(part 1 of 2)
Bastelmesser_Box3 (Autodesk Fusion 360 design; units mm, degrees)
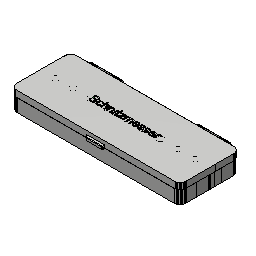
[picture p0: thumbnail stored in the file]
part number: 2025-11-06-15-49-21-213
part number: 2025-11-06-23-53-22-659
part number: 2025-11-06-23-55-04-899
base_feature "Basiselement1" bodies "lid_W150xD95xH20"
move "Verschieben1"
move "Verschieben2"
base_feature "Basiselement1" bodies "box_W150xD95xH20"
delete_face "Fläche löschen1"
delete_face "Fläche löschen2"
delete_face "Fläche löschen3"
delete_face "Fläche löschen4"
delete_face "Fläche löschen1"
delete_face "Fläche löschen2"
move "Verschieben3"
delete_face "Fläche löschen5"
delete_face "Fläche löschen6"
delete_face "Fläche löschen7"
delete_face "Fläche löschen8"
delete_face "Fläche löschen9"
delete_face "Fläche löschen10"
delete_face "Fläche löschen11"
delete_face "Fläche löschen12"
delete_face "Fläche löschen13"
move "Verschieben4"
sketch "Skizze1" plane through (0, 0, 22) normal (0, 0, 1) x axis (-1, 0, 0)
  line L1 (72.9999, 48.1497) -> (-73.0392, 48.1482)
  line L2 (73, 48.1497) -> (72.9999, 48.1497)
  line L3 (73.3517, 48.1236) -> (73, 48.1497)
  line L4 (73.7347, 48.038) -> (73.3517, 48.1236)
  line L5 (74.0994, 47.8936) -> (73.7347, 48.038)
  line L6 (74.4369, 47.694) -> (74.0994, 47.8936)
  line L7 (74.7396, 47.4435) -> (74.4369, 47.694)
  line L8 (74.9982, 47.15) -> (74.7396, 47.4435)
  line L9 (75.2083, 46.8191) -> (74.9982, 47.15)
  line L10 (75.364, 46.4591) -> (75.2083, 46.8191)
  line L11 (75.4616, 46.0789) -> (75.364, 46.4591)
  line L12 (75.4985, 45.6889) -> (75.4616, 46.0789)
  line L13 (75.5, -45.3503) -> (75.4985, 45.6889)
  line L14 (75.4739, -45.702) -> (75.5, -45.3503)
  line L15 (75.3883, -46.085) -> (75.4739, -45.702)
  line L16 (75.2439, -46.4497) -> (75.3883, -46.085)
  line L17 (75.0443, -46.7872) -> (75.2439, -46.4497)
  line L18 (74.795, -47.0886) -> (75.0443, -46.7872)
  line L19 (74.5005, -47.3484) -> (74.795, -47.0886)
  line L20 (74.1693, -47.5585) -> (74.5005, -47.3484)
  line L21 (73.8094, -47.7143) -> (74.1693, -47.5585)
  line L22 (73.4292, -47.8119) -> (73.8094, -47.7143)
  line L23 (73.0392, -47.8487) -> (73.4292, -47.8119)
  line L24 (-73, -47.8503) -> (73.0392, -47.8487)
  line L25 (-73.3517, -47.8242) -> (-73, -47.8503)
  line L26 (-73.7347, -47.7386) -> (-73.3517, -47.8242)
  line L27 (-74.0994, -47.5942) -> (-73.7347, -47.7386)
  line L28 (-74.4369, -47.3945) -> (-74.0994, -47.5942)
  line L29 (-74.7396, -47.144) -> (-74.4369, -47.3945)
  line L30 (-74.9982, -46.8506) -> (-74.7396, -47.144)
  line L31 (-75.2083, -46.5196) -> (-74.9982, -46.8506)
  line L32 (-75.364, -46.1597) -> (-75.2083, -46.5196)
  line L33 (-75.4616, -45.7795) -> (-75.364, -46.1597)
  line L34 (-75.4985, -45.3894) -> (-75.4616, -45.7795)
  line L35 (-75.5, 45.6498) -> (-75.4985, -45.3894)
  line L36 (-75.4739, 46.0014) -> (-75.5, 45.6498)
  line L37 (-75.3883, 46.3845) -> (-75.4739, 46.0014)
  line L38 (-75.2439, 46.7491) -> (-75.3883, 46.3845)
  line L39 (-75.0443, 47.0867) -> (-75.2439, 46.7491)
  line L40 (-74.795, 47.388) -> (-75.0443, 47.0867)
  line L41 (-74.5005, 47.6478) -> (-74.795, 47.388)
  line L42 (-74.1693, 47.858) -> (-74.5005, 47.6478)
  line L43 (-73.8094, 48.0138) -> (-74.1693, 47.858)
  line L44 (-73.4292, 48.1114) -> (-73.8094, 48.0138)
  line L45 (-73.0392, 48.1482) -> (-73.4292, 48.1114)
  line L46 (-78.4013, 47.5848) -> (-77.6325, 48.574)
  line L47 (-78.6417, 46.3723) -> (-78.4013, 47.5848)
  line L48 (-78.3254, 45.1517) -> (-78.6417, 46.3723)
  line L49 (-78.0289, 43.8727) -> (-78.3254, 45.1517)
  line L50 (-77.8472, 42.5936) -> (-78.0289, 43.8727)
  line L51 (-77.8018, 41.3145) -> (-77.8472, 42.5936)
  line L52 (-77.8979, 40.0354) -> (-77.8018, 41.3145)
  line L53 (-78.1243, 38.7563) -> (-77.8979, 40.0354)
  line L54 (-78.4541, 37.4772) -> (-78.1243, 38.7563)
  line L55 (-78.7587, 36.1981) -> (-78.4541, 37.4772)
  line L56 (-78.7368, 34.919) -> (-78.7587, 36.1981)
  line L57 (-78.3554, 33.64) -> (-78.7368, 34.919)
  line L58 (-78.05, 32.361) -> (-78.3554, 33.64)
  line L59 (-77.8568, 31.0819) -> (-78.05, 32.361)
  line L60 (-77.7985, 29.8028) -> (-77.8568, 31.0819)
  line L61 (-77.882, 28.5237) -> (-77.7985, 29.8028)
  line L62 (-78.0974, 27.2446) -> (-77.882, 28.5237)
  line L63 (-78.4192, 25.9655) -> (-78.0974, 27.2446)
  line L64 (-78.7572, 24.6864) -> (-78.4192, 25.9655)
  line L65 (-78.757, 23.4073) -> (-78.7572, 24.6864)
  line L66 (-78.386, 22.1283) -> (-78.757, 23.4073)
  line L67 (-78.072, 20.8492) -> (-78.386, 22.1283)
  line L68 (-77.8674, 19.5702) -> (-78.072, 20.8492)
  line L69 (-77.7963, 18.2911) -> (-77.8674, 19.5702)
  line L70 (-77.8671, 17.012) -> (-77.7963, 18.2911)
  line L71 (-78.0714, 15.7329) -> (-77.8671, 17.012)
  line L72 (-78.3849, 14.4538) -> (-78.0714, 15.7329)
  line L73 (-78.7556, 13.1747) -> (-78.3849, 14.4538)
  line L74 (-78.7555, 11.8956) -> (-78.7556, 13.1747)
  line L75 (-78.4172, 10.6165) -> (-78.7555, 11.8956)
  line L76 (-78.095, 9.3375) -> (-78.4172, 10.6165)
  line L77 (-77.8792, 8.0585) -> (-78.095, 9.3375)
  line L78 (-77.7954, 6.7794) -> (-77.8792, 8.0585)
  line L79 (-77.8533, 5.5003) -> (-77.7954, 6.7794)
  line L80 (-78.0462, 4.2212) -> (-77.8533, 5.5003)
  line L81 (-78.3513, 2.9421) -> (-78.0462, 4.2212)
  line L82 (-78.7323, 1.6629) -> (-78.3513, 2.9421)
  line L83 (-78.7539, 0.3839) -> (-78.7323, 1.6629)
  line L84 (-78.4489, -0.8952) -> (-78.7539, 0.3839)
  line L85 (-78.1188, -2.1742) -> (-78.4489, -0.8952)
  line L86 (-77.8921, -3.4533) -> (-78.1188, -2.1742)
  line L87 (-77.7956, -4.7323) -> (-77.8921, -3.4533)
  line L88 (-77.8407, -6.0114) -> (-77.7956, -4.7323)
  line L89 (-78.0221, -7.2905) -> (-77.8407, -6.0114)
  line L90 (-78.3182, -8.5696) -> (-78.0221, -7.2905)
  line L91 (-78.6941, -9.8488) -> (-78.3182, -8.5696)
  line L92 (-78.7524, -11.1279) -> (-78.6941, -9.8488)
  line L93 (-78.4812, -12.4069) -> (-78.7524, -11.1279)
  line L94 (-78.1435, -13.6859) -> (-78.4812, -12.4069)
  line L95 (-77.906, -14.965) -> (-78.1435, -13.6859)
  line L96 (-77.797, -16.244) -> (-77.906, -14.965)
  line L97 (-77.8292, -17.5231) -> (-77.797, -16.244)
  line L98 (-77.9988, -18.8022) -> (-77.8292, -17.5231)
  line L99 (-78.2858, -20.0814) -> (-77.9988, -18.8022)
  line L100 (-78.6562, -21.3605) -> (-78.2858, -20.0814)
  line L101 (-78.7508, -22.6396) -> (-78.6562, -21.3605)
  line L102 (-78.5141, -23.9186) -> (-78.7508, -22.6396)
  line L103 (-78.169, -25.1977) -> (-78.5141, -23.9186)
  line L104 (-77.9211, -26.4767) -> (-78.169, -25.1977)
  line L105 (-77.7996, -27.7558) -> (-77.9211, -26.4767)
  line L106 (-77.8188, -29.0348) -> (-77.7996, -27.7558)
  line L107 (-77.9766, -30.3139) -> (-77.8188, -29.0348)
  line L108 (-78.2541, -31.5931) -> (-77.9766, -30.3139)
  line L109 (-78.6186, -32.8722) -> (-78.2541, -31.5931)
  line L110 (-78.7493, -34.1513) -> (-78.6186, -32.8722)
  line L111 (-78.5473, -35.4303) -> (-78.7493, -34.1513)
  line L112 (-78.1953, -36.7094) -> (-78.5473, -35.4303)
  line L113 (-77.9372, -37.9884) -> (-78.1953, -36.7094)
  line L114 (-77.8033, -39.2675) -> (-77.9372, -37.9884)
  line L115 (-77.8096, -40.5466) -> (-77.8033, -39.2675)
  line L116 (-77.9553, -41.8257) -> (-77.8096, -40.5466)
  line L117 (-78.2231, -43.1048) -> (-77.9553, -41.8257)
  line L118 (-78.5814, -44.3839) -> (-78.2231, -43.1048)
  line L119 (-78.7497, -45.6324) -> (-78.5814, -44.3839)
  line L120 (-78.3789, -46.8062) -> (-78.7497, -45.6324)
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  dimension "d1" = -3.25
extrude "Extrusion1" new body sketch "Skizze1" against normal blind 22
combine "Kombinieren1"
work_plane "Arbeitsebene1" AlongDistance 0
extrude "Extrusion1" add of existing geometry blind 5.536
work_plane "Arbeitsebene1" AlongDistance -18.9338
split "Teilen1" bodies "lid_W150xD95xH20 (1)"
work_plane "Arbeitsebene2" AlongDistance 47
split "Teilen2" bodies "lid_W150xD95xH20 (1) (1)"
move "Verschieben1"
combine "Kombinieren2" bodies "box_W150xD95xH20 (2) (1)"
move "Verschieben5"
combine "Kombinieren1" bodies "lid_W150xD95xH20 (1) (1)"
delete_face "Fläche löschen14"
work_plane "Arbeitsebene2" AlongDistance 0
split "Teilen4" bodies "box_W150xD95xH20 (1)", "box_W150xD95xH20 (3)", "box_W150xD95xH20 (4)", "box_W150xD95xH20 (5)", "box_W150xD95xH20 (6)", "box_W150xD95xH20 (7)", "box_W150xD95xH20 (8)", "box_W150xD95xH20 (9)"
remove_body "Körper entfernen3"
remove_body "Körper entfernen4"
offset_faces "Flächen versetzen1" distance 10
offset_faces "Flächen versetzen2" distance -10
remove_body "Körper entfernen5"
remove_body "Körper entfernen6"
remove_body "Körper entfernen7"
remove_body "Körper entfernen8"
remove_body "Körper entfernen9"
remove_body "Körper entfernen10"
remove_body "Körper entfernen11"
remove_body "Körper entfernen12"
remove_body "Körper entfernen13"
remove_body "Körper entfernen14"
remove_body "Körper entfernen15"
remove_body "Körper entfernen16"
work_plane "Arbeitsebene3" AlongDistance 0
split "Teilen5" bodies "box_W150xD95xH20 (1)", "box_W150xD95xH20 (2)", "box_W150xD95xH20 (3)"
remove_body "Körper entfernen17"
remove_body "Körper entfernen18"
remove_body "Körper entfernen19"
sketch "Skizze2" plane through (0, 0, 22) normal (0, 0, 1) x axis (-1, 0, 0)
  line L1 (75.5, -45.3503) -> (75.4997, -28.0662)
  line L2 (75.4739, -45.702) -> (75.5, -45.3503)
  line L3 (75.3883, -46.085) -> (75.4739, -45.702)
  line L4 (75.2439, -46.4497) -> (75.3883, -46.085)
  line L5 (75.0443, -46.7872) -> (75.2439, -46.4497)
  line L6 (74.795, -47.0886) -> (75.0443, -46.7872)
  line L7 (74.5005, -47.3484) -> (74.795, -47.0886)
  line L8 (74.1693, -47.5585) -> (74.5005, -47.3484)
  line L9 (73.8094, -47.7143) -> (74.1693, -47.5585)
  line L10 (73.4292, -47.8119) -> (73.8094, -47.7143)
  line L11 (73.0392, -47.8487) -> (73.4292, -47.8119)
  line L12 (-73, -47.8503) -> (73.0392, -47.8487)
  line L13 (-73.3517, -47.8242) -> (-73, -47.8503)
  line L14 (-73.7347, -47.7386) -> (-73.3517, -47.8242)
  line L15 (-74.0994, -47.5942) -> (-73.7347, -47.7386)
  line L16 (-74.4369, -47.3945) -> (-74.0994, -47.5942)
  line L17 (-74.7396, -47.144) -> (-74.4369, -47.3945)
  line L18 (-74.9982, -46.8506) -> (-74.7396, -47.144)
  line L19 (-75.2083, -46.5196) -> (-74.9982, -46.8506)
  line L20 (-75.364, -46.1597) -> (-75.2083, -46.5196)
  line L21 (-75.4616, -45.7795) -> (-75.364, -46.1597)
  line L22 (-75.4985, -45.3894) -> (-75.4616, -45.7795)
  line L23 (-75.4988, -28.0662) -> (-75.4985, -45.3894)
  line L24 (-75.4995, -28.0662) -> (-75.4988, -28.0662)
  line L25 (-75.5, -1.3502) -> (-75.4995, -28.0662)
  line L26 (-75.4739, -0.9986) -> (-75.5, -1.3502)
  line L27 (-75.3883, -0.6155) -> (-75.4739, -0.9986)
  line L28 (-75.2439, -0.2509) -> (-75.3883, -0.6155)
  line L29 (-75.0443, 0.0867) -> (-75.2439, -0.2509)
  line L30 (-74.795, 0.388) -> (-75.0443, 0.0867)
  line L31 (-74.5005, 0.6478) -> (-74.795, 0.388)
  line L32 (-74.1693, 0.858) -> (-74.5005, 0.6478)
  line L33 (-73.8094, 1.0138) -> (-74.1693, 0.858)
  line L34 (-73.4292, 1.1114) -> (-73.8094, 1.0138)
  line L35 (-73.0392, 1.1482) -> (-73.4292, 1.1114)
  line L36 (72.9999, 1.1497) -> (-73.0392, 1.1482)
  line L37 (73, 1.1497) -> (72.9999, 1.1497)
  line L38 (73.3517, 1.1236) -> (73, 1.1497)
  line L39 (73.7347, 1.038) -> (73.3517, 1.1236)
  line L40 (74.0994, 0.8936) -> (73.7347, 1.038)
  line L41 (74.4369, 0.694) -> (74.0994, 0.8936)
  line L42 (74.7396, 0.4435) -> (74.4369, 0.694)
  line L43 (74.9982, 0.15) -> (74.7396, 0.4435)
  line L44 (75.2083, -0.1809) -> (74.9982, 0.15)
  line L45 (75.364, -0.5409) -> (75.2083, -0.1809)
  line L46 (75.4616, -0.9211) -> (75.364, -0.5409)
  line L47 (75.4985, -1.3111) -> (75.4616, -0.9211)
  line L48 (75.4989, -28.0662) -> (75.4985, -1.3111)
  line L49 (75.4997, -28.0662) -> (75.4989, -28.0662)
  line L50 (-73.1923, 4.3982) -> (73.1205, 4.3997)
  line L51 (-73.9894, 4.3229) -> (-73.1923, 4.3982)
  line L52 (-74.8653, 4.0981) -> (-73.9894, 4.3229)
  line L53 (-75.6949, 3.7391) -> (-74.8653, 4.0981)
  line L54 (-76.4582, 3.2546) -> (-75.6949, 3.7391)
  line L55 (-77.1366, 2.6563) -> (-76.4582, 3.2546)
  line L56 (-77.7116, 1.961) -> (-77.1366, 2.6563)
  line L57 (-78.1715, 1.1835) -> (-77.7116, 1.961)
  line L58 (-78.5043, 0.343) -> (-78.1715, 1.1835)
  line L59 (-78.6974, -0.5214) -> (-78.5043, 0.343)
  line L60 (-78.75, -1.2298) -> (-78.6974, -0.5214)
  line L61 (-78.7498, -10.7646) -> (-78.75, -1.2298)
  line L62 (-78.7587, -10.8019) -> (-78.7498, -10.7646)
  line L63 (-78.7498, -11.3207) -> (-78.7587, -10.8019)
  line L64 (-78.7496, -22.2851) -> (-78.7498, -11.3207)
  line L65 (-78.7572, -22.3136) -> (-78.7496, -22.2851)
  line L66 (-78.757, -23.5927) -> (-78.7572, -22.3136)
  line L67 (-78.7496, -23.6181) -> (-78.757, -23.5927)
  line L68 (-78.7495, -28.0662) -> (-78.7496, -23.6181)
  line L69 (-78.7488, -28.0662) -> (-78.7495, -28.0662)
  line L70 (-78.7487, -34.1454) -> (-78.7488, -28.0662)
  line L71 (-78.7493, -34.1513) -> (-78.7487, -34.1454)
  line L72 (-78.7487, -34.1551) -> (-78.7493, -34.1513)
  line L73 (-78.7485, -45.5426) -> (-78.7487, -34.1551)
  line L74 (-78.744, -45.5898) -> (-78.7485, -45.5426)
  line L75 (-78.7497, -45.6324) -> (-78.744, -45.5898)
  line L76 (-78.7358, -45.6765) -> (-78.7497, -45.6324)
  line L77 (-78.6732, -46.3397) -> (-78.7358, -45.6765)
  line L78 (-78.4484, -47.2156) -> (-78.6732, -46.3397)
  line L79 (-78.0894, -48.0451) -> (-78.4484, -47.2156)
  line L80 (-77.6054, -48.8077) -> (-78.0894, -48.0451)
  line L81 (-77.0087, -49.4847) -> (-77.6054, -48.8077)
  line L82 (-76.3119, -50.0615) -> (-77.0087, -49.4847)
  line L83 (-75.5337, -50.5217) -> (-76.3119, -50.0615)
  line L84 (-74.6932, -50.8545) -> (-75.5337, -50.5217)
  line L85 (-73.8289, -51.0477) -> (-74.6932, -50.8545)
  line L86 (-73.1205, -51.1003) -> (-73.8289, -51.0477)
  line L87 (-70.6456, -51.1002) -> (-73.1205, -51.1003)
  line L88 (-70.5833, -51.1101) -> (-70.6456, -51.1002)
  line L89 (-70.4873, -51.1002) -> (-70.5833, -51.1101)
  line L90 (-64.3433, -51.1002) -> (-70.4873, -51.1002)
  line L91 (-64.3433, -51.8441) -> (-64.3433, -51.1002)
  line L92 (-58.3433, -51.8441) -> (-64.3433, -51.8441)
  line L93 (-58.3433, -51.1001) -> (-58.3433, -51.8441)
  line L94 (-47.5994, -51.1) -> (-58.3433, -51.1001)
  line L95 (-47.561, -51.1081) -> (-47.5994, -51.1)
  line L96 (-47.3834, -51.1) -> (-47.561, -51.1081)
  line L97 (-41.3433, -51.0999) -> (-47.3834, -51.1)
  line L98 (-41.3433, -51.8441) -> (-41.3433, -51.0999)
  line L99 (-35.3433, -51.8441) -> (-41.3433, -51.8441)
  line L100 (-35.3433, -51.0999) -> (-35.3433, -51.8441)
  line L101 (-24.5609, -51.0998) -> (-35.3433, -51.0999)
  line L102 (-24.5366, -51.1062) -> (-24.5609, -51.0998)
  line L103 (-23.2573, -51.1061) -> (-24.5366, -51.1062)
  line L104 (-23.2355, -51.0997) -> (-23.2573, -51.1061)
  line L105 (-13.0448, -51.0996) -> (-23.2355, -51.0997)
  line L106 (-13.0255, -51.1052) -> (-13.0448, -51.0996)
  line L107 (-11.7462, -51.1051) -> (-13.0255, -51.1052)
  line L108 (-11.7254, -51.0996) -> (-11.7462, -51.1051)
  line L109 (-0.5072, -51.0995) -> (-11.7254, -51.0996)
  line L110 (-0.2329, -51.1041) -> (-0.5072, -51.0995)
  line L111 (-0.2134, -51.0995) -> (-0.2329, -51.1041)
  line L112 (11.1949, -51.0994) -> (-0.2134, -51.0995)
  line L113 (11.2782, -51.1032) -> (11.1949, -51.0994)
  line L114 (11.2962, -51.0994) -> (11.2782, -51.1032)
  line L115 (22.7494, -51.0993) -> (11.2962, -51.0994)
  line L116 (22.7894, -51.1022) -> (22.7494, -51.0993)
  line L117 (22.8053, -51.0993) -> (22.7894, -51.1022)
  line L118 (34.2821, -51.0991) -> (22.8053, -51.0993)
  line L119 (34.3027, -51.1012) -> (34.2821, -51.0991)
  line L120 (34.316, -51.0991) -> (34.3027, -51.1012)
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  dimension "d14" = -1.25
extrude "Extrusion2" cut sketch "Skizze2" against normal blind 10
sketch "Skizze3" plane through (0, 0, 10) normal (0, 0, -1) x axis (1, 0, 0)
  line L1 (-73.1205, 4.3997) -> (73.1923, 4.3982)
  line L2 (-73.8289, 4.3472) -> (-73.1205, 4.3997)
  line L3 (-74.6933, 4.154) -> (-73.8289, 4.3472)
  line L4 (-75.5337, 3.8212) -> (-74.6933, 4.154)
  line L5 (-76.3118, 3.361) -> (-75.5337, 3.8212)
  line L6 (-77.0087, 2.7842) -> (-76.3118, 3.361)
  line L7 (-77.6054, 2.1072) -> (-77.0087, 2.7842)
  line L8 (-78.0894, 1.3445) -> (-77.6054, 2.1072)
  line L9 (-78.4484, 0.515) -> (-78.0894, 1.3445)
  line L10 (-78.6732, -0.3609) -> (-78.4484, 0.515)
  line L11 (-78.7358, -1.024) -> (-78.6732, -0.3609)
  line L12 (-78.7497, -1.0681) -> (-78.7358, -1.024)
  line L13 (-78.744, -1.1107) -> (-78.7497, -1.0681)
  line L14 (-78.7485, -1.1579) -> (-78.744, -1.1107)
  line L15 (-78.7487, -12.5454) -> (-78.7485, -1.1579)
  line L16 (-78.7493, -12.5492) -> (-78.7487, -12.5454)
  line L17 (-78.7487, -12.5551) -> (-78.7493, -12.5492)
  line L18 (-78.7488, -24.0504) -> (-78.7487, -12.5551)
  line L19 (-78.7508, -24.0609) -> (-78.7488, -24.0504)
  line L20 (-78.7488, -24.0874) -> (-78.7508, -24.0609)
  line L21 (-78.7489, -28.0662) -> (-78.7488, -24.0874)
  line L22 (-78.7497, -28.0662) -> (-78.7489, -28.0662)
  line L23 (-78.7498, -35.3798) -> (-78.7497, -28.0662)
  line L24 (-78.7587, -35.8986) -> (-78.7498, -35.3798)
  line L25 (-78.7498, -35.936) -> (-78.7587, -35.8986)
  line L26 (-78.75, -45.4708) -> (-78.7498, -35.936)
  line L27 (-78.6974, -46.1792) -> (-78.75, -45.4708)
  line L28 (-78.5043, -47.0435) -> (-78.6974, -46.1792)
  line L29 (-78.1715, -47.884) -> (-78.5043, -47.0435)
  line L30 (-77.7116, -48.6616) -> (-78.1715, -47.884)
  line L31 (-77.1366, -49.3569) -> (-77.7116, -48.6616)
  line L32 (-76.4582, -49.9551) -> (-77.1366, -49.3569)
  line L33 (-75.6949, -50.4396) -> (-76.4582, -49.9551)
  line L34 (-74.8653, -50.7986) -> (-75.6949, -50.4396)
  line L35 (-73.9894, -51.0234) -> (-74.8653, -50.7986)
  line L36 (-73.1923, -51.0987) -> (-73.9894, -51.0234)
  line L37 (-64.6567, -51.0988) -> (-73.1923, -51.0987)
  line L38 (-64.6567, -50.2369) -> (-64.6567, -51.0988)
  line L39 (-64.4198, -50.2144) -> (-64.6567, -50.2369)
  line L40 (-63.7212, -50.1482) -> (-64.4198, -50.2144)
  line L41 (-62.4419, -50.1678) -> (-63.7212, -50.1482)
  line L42 (-61.1626, -50.3258) -> (-62.4419, -50.1678)
  line L43 (-59.8834, -50.6036) -> (-61.1626, -50.3258)
  line L44 (-59.534, -50.7032) -> (-59.8834, -50.6036)
  line L45 (-58.6567, -50.9534) -> (-59.534, -50.7032)
  line L46 (-58.6567, -51.0989) -> (-58.6567, -50.9534)
  line L47 (-57.329, -51.0989) -> (-58.6567, -51.0989)
  line L48 (-57.3249, -51.0993) -> (-57.329, -51.0989)
  line L49 (-57.3223, -51.0989) -> (-57.3249, -51.0993)
  line L50 (-45.8235, -51.099) -> (-57.3223, -51.0989)
  line L51 (-45.8138, -51.1003) -> (-45.8235, -51.099)
  line L52 (-45.8041, -51.099) -> (-45.8138, -51.1003)
  line L53 (-41.6567, -51.0991) -> (-45.8041, -51.099)
  line L54 (-41.6567, -50.2713) -> (-41.6567, -51.0991)
  line L55 (-41.4118, -50.2434) -> (-41.6567, -50.2713)
  line L56 (-40.6967, -50.162) -> (-41.4118, -50.2434)
  line L57 (-39.4174, -50.1556) -> (-40.6967, -50.162)
  line L58 (-38.1382, -50.2893) -> (-39.4174, -50.1556)
  line L59 (-36.8589, -50.5474) -> (-38.1382, -50.2893)
  line L60 (-36.5133, -50.6425) -> (-36.8589, -50.5474)
  line L61 (-35.6567, -50.8782) -> (-36.5133, -50.6425)
  line L62 (-35.6567, -51.0991) -> (-35.6567, -50.8782)
  line L63 (-34.316, -51.0991) -> (-35.6567, -51.0991)
  line L64 (-34.3027, -51.1012) -> (-34.316, -51.0991)
  line L65 (-34.2821, -51.0991) -> (-34.3027, -51.1012)
  line L66 (-22.8053, -51.0993) -> (-34.2821, -51.0991)
  line L67 (-22.7894, -51.1022) -> (-22.8053, -51.0993)
  line L68 (-22.7494, -51.0993) -> (-22.7894, -51.1022)
  line L69 (-11.2962, -51.0994) -> (-22.7494, -51.0993)
  line L70 (-11.2782, -51.1032) -> (-11.2962, -51.0994)
  line L71 (-11.1949, -51.0994) -> (-11.2782, -51.1032)
  line L72 (0.2134, -51.0995) -> (-11.1949, -51.0994)
  line L73 (0.2329, -51.1041) -> (0.2134, -51.0995)
  line L74 (0.5072, -51.0995) -> (0.2329, -51.1041)
  line L75 (11.7254, -51.0996) -> (0.5072, -51.0995)
  line L76 (11.7462, -51.1051) -> (11.7254, -51.0996)
  line L77 (13.0255, -51.1052) -> (11.7462, -51.1051)
  line L78 (13.0448, -51.0996) -> (13.0255, -51.1052)
  line L79 (23.2355, -51.0997) -> (13.0448, -51.0996)
  line L80 (23.2573, -51.1061) -> (23.2355, -51.0997)
  line L81 (24.5366, -51.1062) -> (23.2573, -51.1061)
  line L82 (24.5609, -51.0998) -> (24.5366, -51.1062)
  line L83 (35.3433, -51.0999) -> (24.5609, -51.0998)
  line L84 (35.3433, -51.0951) -> (35.3433, -51.0999)
  line L85 (35.4662, -51.0972) -> (35.3433, -51.0951)
  line L86 (35.5533, -51.0987) -> (35.4662, -51.0972)
  line L87 (36.0477, -51.1072) -> (35.5533, -51.0987)
  line L88 (37.327, -50.8025) -> (36.0477, -51.1072)
  line L89 (38.6063, -50.4726) -> (37.327, -50.8025)
  line L90 (39.8856, -50.2462) -> (38.6063, -50.4726)
  line L91 (41.1648, -50.15) -> (39.8856, -50.2462)
  line L92 (41.3433, -50.1563) -> (41.1648, -50.15)
  line L93 (41.3433, -51.0999) -> (41.3433, -50.1563)
  line L94 (47.3834, -51.1) -> (41.3433, -51.0999)
  line L95 (47.561, -51.1081) -> (47.3834, -51.1)
  line L96 (47.5994, -51.1) -> (47.561, -51.1081)
  line L97 (58.3433, -51.1001) -> (47.5994, -51.1)
  line L98 (58.3433, -51.055) -> (58.3433, -51.1001)
  line L99 (58.4907, -51.066) -> (58.3433, -51.055)
  line L100 (58.5592, -51.071) -> (58.4907, -51.066)
  line L101 (59.0722, -51.1091) -> (58.5592, -51.071)
  line L102 (60.3514, -50.8726) -> (59.0722, -51.1091)
  line L103 (61.6307, -50.5278) -> (60.3514, -50.8726)
  line L104 (62.91, -50.2802) -> (61.6307, -50.5278)
  line L105 (64.1893, -50.159) -> (62.91, -50.2802)
  line L106 (64.3433, -50.1613) -> (64.1893, -50.159)
  line L107 (64.3433, -51.1002) -> (64.3433, -50.1613)
  line L108 (70.4873, -51.1002) -> (64.3433, -51.1002)
  line L109 (70.5833, -51.1101) -> (70.4873, -51.1002)
  line L110 (70.6456, -51.1002) -> (70.5833, -51.1101)
  line L111 (73.1205, -51.1003) -> (70.6456, -51.1002)
  line L112 (73.8289, -51.0477) -> (73.1205, -51.1003)
  line L113 (74.6932, -50.8545) -> (73.8289, -51.0477)
  line L114 (75.5337, -50.5217) -> (74.6932, -50.8545)
  line L115 (76.3119, -50.0615) -> (75.5337, -50.5217)
  line L116 (77.0087, -49.4847) -> (76.3119, -50.0615)
  line L117 (77.6054, -48.8077) -> (77.0087, -49.4847)
  line L118 (78.0894, -48.0451) -> (77.6054, -48.8077)
  line L119 (78.4484, -47.2156) -> (78.0894, -48.0451)
  line L120 (78.6732, -46.3397) -> (78.4484, -47.2156)
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  point P48 (-58.6567, -51.0989)
  point P149 (-58.6567, -51.0989)
  point P64 (-35.6567, -51.0991)
  point P153 (-35.6567, -51.0991)
  point P95 (41.3433, -51.0999)
  point P157 (41.3433, -51.0999)
  point P109 (64.3433, -51.1002)
  point P161 (64.3433, -51.1002)
  coincident P48 P149
  coincident P64 P153
  coincident P95 P157
  coincident P109 P161
extrude "Extrusion3" add sketch "Skizze3" against normal blind 5.717
extrude "Extrusion4" add sketch "Skizze3" against normal blind 4.878
extrude "Extrusion5" add sketch "Skizze3" against normal blind 5.291
extrude "Extrusion6" add sketch "Skizze3" against normal blind 5.325
sketch "Skizze4" plane through (0, 0, 22) normal (0, 0, 1) x axis (-1, 0, 0)
work_plane "Arbeitsebene4" AlongDistance 0
sketch "Skizze5" plane through (0, 0, 22) normal (0, 0, 1) x axis (1, 0, 0)
  line L1 (73.0981, -2.3982) -> (-73.0463, -2.3997)
  line L2 (73.6447, -2.3466) -> (73.0981, -2.3982)
  line L3 (74.2155, -2.2001) -> (73.6447, -2.3466)
  line L4 (74.7561, -1.9661) -> (74.2155, -2.2001)
  line L5 (75.2534, -1.6505) -> (74.7561, -1.9661)
  line L6 (75.6956, -1.2605) -> (75.2534, -1.6505)
  line L7 (76.0702, -0.8076) -> (75.6956, -1.2605)
  line L8 (76.3699, -0.3008) -> (76.0702, -0.8076)
  line L9 (76.5868, 0.2469) -> (76.3699, -0.3008)
  line L10 (76.7137, 0.815) -> (76.5868, 0.2469)
  line L11 (76.75, 1.3039) -> (76.7137, 0.815)
  line L12 (76.7495, 29.3162) -> (76.75, 1.3039)
  line L13 (76.7487, 29.3162) -> (76.7495, 29.3162)
  line L14 (76.7485, 45.4483) -> (76.7487, 29.3162)
  line L15 (76.6968, 45.9949) -> (76.7485, 45.4483)
  line L16 (76.5503, 46.5658) -> (76.6968, 45.9949)
  line L17 (76.3164, 47.1063) -> (76.5503, 46.5658)
  line L18 (76.001, 47.6033) -> (76.3164, 47.1063)
  line L19 (75.6123, 48.0443) -> (76.001, 47.6033)
  line L20 (75.1581, 48.4203) -> (75.6123, 48.0443)
  line L21 (74.6511, 48.7202) -> (75.1581, 48.4203)
  line L22 (74.1034, 48.937) -> (74.6511, 48.7202)
  line L23 (73.5352, 49.064) -> (74.1034, 48.937)
  line L24 (73.0463, 49.1003) -> (73.5352, 49.064)
  line L25 (-73.0981, 49.0987) -> (73.0463, 49.1003)
  line L26 (-73.6446, 49.0471) -> (-73.0981, 49.0987)
  line L27 (-74.2155, 48.9006) -> (-73.6446, 49.0471)
  line L28 (-74.7561, 48.6666) -> (-74.2155, 48.9006)
  line L29 (-75.2534, 48.351) -> (-74.7561, 48.6666)
  line L30 (-75.6956, 47.961) -> (-75.2534, 48.351)
  line L31 (-76.0702, 47.5081) -> (-75.6956, 47.961)
  line L32 (-76.3699, 47.0013) -> (-76.0702, 47.5081)
  line L33 (-76.5868, 46.4537) -> (-76.3699, 47.0013)
  line L34 (-76.7137, 45.8855) -> (-76.5868, 46.4537)
  line L35 (-76.75, 45.3967) -> (-76.7137, 45.8855)
  line L36 (-76.7497, 26.8162) -> (-76.75, 45.3967)
  line L37 (-76.7489, 26.8162) -> (-76.7497, 26.8162)
  line L38 (-76.7485, 1.2522) -> (-76.7489, 26.8162)
  line L39 (-76.6968, 0.7056) -> (-76.7485, 1.2522)
  line L40 (-76.5503, 0.1347) -> (-76.6968, 0.7056)
  line L41 (-76.3164, -0.4058) -> (-76.5503, 0.1347)
  line L42 (-76.001, -0.9028) -> (-76.3164, -0.4058)
  line L43 (-75.6123, -1.3438) -> (-76.001, -0.9028)
  line L44 (-75.158, -1.7198) -> (-75.6123, -1.3438)
  line L45 (-74.6511, -2.0196) -> (-75.158, -1.7198)
  line L46 (-74.1034, -2.2365) -> (-74.6511, -2.0196)
  line L47 (-73.5352, -2.3634) -> (-74.1034, -2.2365)
  line L48 (-73.0463, -2.3997) -> (-73.5352, -2.3634)
  line L49 (55.7492, 23.3754) -> (76.7492, 23.3761)
  line L50 (55.7492, 33.8244) -> (55.7492, 15.5898)
  line L51 (14.7491, 26.378) -> (76.7491, 26.378)
  line L52 (-42.2502, 19.6259) -> (76.7498, 19.63)
  line L53 (14.7491, 33.747) -> (14.7491, 19.6279)
  line L54 (-42.2507, 32.7176) -> (-42.2502, 19.6259)
  line L55 (0.0258, 9.2563) -> (0.0259, -3.399)
  line L56 (73.0981, -3.3982) -> (-73.0463, -3.3997)
  line L57 (-3.5241, -2.399) -> (-3.5241, -0.4365)
  line L58 (3.5759, -2.3989) -> (3.5759, -0.4365)
  line L59 (-76.7485, 3.79) -> (-74.2023, 3.7821)
  line L60 (-70.588, -2.3997) -> (-70.5868, 0.1537)
  line L61 (-76.7485, 3.79) -> (-76.7485, 4.3758)
  line L62 (70.7336, -2.3982) -> (70.7209, 0.195)
  line L63 (76.75, 3.7685) -> (74.2623, 3.7625)
  line L64 (72.6939, -2.3982) -> (70.7336, -2.3982)
  line L65 (-72.5481, -2.3997) -> (-70.588, -2.3997)
  line L66 (-76.7485, 1.8514) -> (-76.7485, 3.79)
  line L67 (-2.3089, -2.399) -> (-3.5241, -2.399)
  line L68 (2.3606, -2.3989) -> (3.5759, -2.3989)
  line L69 (76.75, 3.7685) -> (76.6222, 3.7681)
  line L70 (76.75, 3.7685) -> (76.75, 1.9891)
  circle C1 centre (0.0259, -0.4365) radius 3.05
  arc A1 centre (-73.6899, 0.5362) radius 3.4648 clockwise from (-73.6883, 4.0011) to (-73.654, 4.0009)
  arc A2 centre (0.0259, -0.4365) radius 3.55 clockwise from (-3.5241, -0.4365) to (3.5759, -0.4365)
  arc A3 centre (-73.0062, 1.3434) radius 4.7433 clockwise from (-73.057, -3.3997) to (-77.7482, 1.2278)
  circle C2 centre (-74.2135, 0.1554) radius 3.05
  arc A4 centre (-74.2135, 0.1554) radius 3.6267 clockwise from (-74.2023, 3.7821) to (-70.5868, 0.1537)
  arc A5 centre (73.0069, 1.344) radius 4.7433 clockwise from (77.7499, 1.2932) to (73.1224, -3.3979)
  circle C3 centre (74.2708, 0.2125) radius 3.05
  arc A6 centre (74.2708, 0.2125) radius 3.55 clockwise from (76.7499, 2.7535) to (76.75, 2.7534)
  arc A7 centre (74.2708, 0.2125) radius 3.55 clockwise from (70.7209, 0.195) to (74.2623, 3.7625)
  point P58 (14.7491, 19.6279)
  point P64 (0.0259, -3.399)
  point P63 (0.0259, -0.4365)
  point P74 (-3.5241, -2.399)
  point P76 (3.5759, -2.3989)
  point P84 (-70.5868, 0.1537)
  point P85 (-70.588, -2.3997)
  point P86 (-70.5868, 0.1537)
  point P92 (70.7209, 0.195)
  point P93 (70.7336, -2.3982)
  point P94 (74.2623, 3.7625)
  point P98 (72.6939, -2.3982)
  point P99 (-72.5481, -2.3997)
  point P100 (-76.7485, 1.8514)
  point P101 (-2.3089, -2.399)
  point P102 (2.3606, -2.3989)
  point P103 (76.6222, 3.7681)
  point P104 (76.75, 3.7685)
  point P105 (76.75, 1.9891)
  point P50 (76.7492, 23.3761)
  point P51 (55.7492, 23.3754)
  point P54 (76.7491, 26.378)
  point P55 (14.7491, 26.378)
  point P56 (76.7498, 19.63)
  point P57 (-42.2502, 19.6259)
  vertical L50
  perpendicular L50 L51
  coincident L52 P58
  perpendicular L52 L54
  midpoint P64 L56
  perpendicular L55 L56
  coincident P63 L55
  coincident L1 P74
  perpendicular L1 L57
  coincident L1 P76
  perpendicular L1 L58
  tangent L57 A2
  tangent L58 A2
  concentric C1 A2
  coincident P84 A4
  coincident L1 P85
  concentric C2 A4
  coincident L60 P86
  tangent L59 A4
  tangent L60 A4
  coincident P92 A6
  coincident L1 P93
  tangent L62 A6
  coincident P94 A6
  concentric C3 A6
  concentric A6 A7
  coincident L1 P98
  coincident C3 P98
  coincident L1 P99
  coincident C2 P99
  coincident C2 P100
  coincident L38 P100
  parallel L38 L66
  coincident C1 P101
  perpendicular L57 L67
  coincident C1 P102
  perpendicular L58 L68
  tangent L63 A7
  coincident L63 P103
  coincident L12 P104
  coincident C3 P105
  coincident L12 P105
  dimension "d26" distance P50 P51 = 21
  dimension "d30" distance P54 P55 = 62
  dimension "d31" distance P56 P57 = 119
  dimension "d45" diameter C1 = 6.1
  dimension "d59" diameter C2 = 6.1
  dimension "d62" diameter C3 = 6.1
web "Steg" Thickness 0.6 FilletRadius 0
sketch "Skizze6" plane through (56.0492, 0, 0) normal (1, 0, 0) x axis (0, 1, 0)
  line L1 (49.1001, 22) -> (49.1001, 12)
  line L2 (-2.3984, 22) -> (49.1001, 22)
  line L3 (-2.3984, 12) -> (-2.3984, 22)
  line L4 (49.1001, 12) -> (-2.3984, 12)
  line L5 (49.1001, 22) -> (-2.3984, 22)
  line L6 (49.1001, 17) -> (49.1001, 22)
  line L7 (-2.3984, 17) -> (49.1001, 17)
  line L8 (-2.3984, 22) -> (-2.3984, 17)
  point P8 (49.1001, 17)
  point P4 (-2.3984, 22)
  point P6 (-2.3984, 22)
  point P9 (-2.3984, 17)
  horizontal L5
  vertical L6
  horizontal L7
  vertical L8
  coincident L1 P8
  coincident P4 P6
  dimension "d32" distance P6 P9 = 5
extrude "Extrusion7" cut sketch "Skizze6" profile of L1 L2 L3 L5 L6 L7 L8 against normal blind 100.621
sketch "Skizze7" plane through (0, 0, 17) normal (0, 0, 1) x axis (-1, 0, 0)
  line L1 (-55.4492, 2.3984) -> (-55.4492, -49.1001)
  line L2 (-56.0492, 2.3984) -> (-55.4492, 2.3984)
  line L3 (-56.0492, -49.1001) -> (-56.0492, 2.3984)
  line L4 (-55.4492, -49.1001) -> (-56.0492, -49.1001)
  line L5 (-55.7492, -38.1001) -> (-55.7492, -49.1001)
  line L6 (-55.5927, -24.1001) -> (-55.5927, -49.1001)
  line L7 (-55.7492, -9.6016) -> (-55.7492, 2.3984)
  point P6 (-55.7492, -49.1001)
  point P8 (-55.5927, -49.1001)
  point P10 (-55.7492, 2.3984)
  point P7 (-55.7492, -38.1001)
  point P9 (-55.5927, -24.1001)
  point P11 (-55.7492, -9.6016)
  midpoint L4 P6
  perpendicular L4 L5
  coincident L4 P8
  perpendicular L4 L6
  midpoint L2 P10
  perpendicular L2 L7
  dimension "d35" distance P6 P7 = 11
  dimension "d36" distance P8 P9 = 25
  dimension "d37" distance P10 P11 = 12
sketch "Skizze8" plane through (56.0492, 0, 0) normal (1, 0, 0) x axis (0, 1, 0)
  line L1 (-2.3984, 17) -> (49.1001, 17)
  line L2 (-2.3984, 12) -> (-2.3984, 17)
  line L3 (49.1001, 12) -> (-2.3984, 12)
  line L4 (49.1001, 17) -> (49.1001, 12)
  circle C1 centre (9.5657, 17) radius 5
  circle C2 centre (24.1087, 17) radius 5
  circle C3 centre (38.062, 17) radius 5
  point P6 (9.5657, 17)
  point P7 (24.1087, 17)
  point P8 (38.062, 17)
  coincident L1 P6
  coincident L1 P7
  coincident L1 P8
  dimension "d38" diameter C1 = 10
  dimension "d41" diameter C2 = 10
  dimension "d42" diameter C3 = 10
extrude "Extrusion11" cut sketch "Skizze5" profile of L1 L38 L39 L40 L41 L42 L43 L44 L45 L46 L47 L48 C2 against normal blind 10
extrude "Extrusion12" cut sketch "Skizze5" profile of L1 C1 against normal blind 10
extrude "Extrusion13" add sketch "Skizze5" profile of L1 C1 A2 L57 L58 against normal blind 10
extrude "Extrusion14" cut sketch "Skizze5" profile of L1 C1 against normal blind 2.2
extrude "Extrusion15" add sketch "Skizze5" profile of L1 L2 L3 L4 L5 L6 L7 L8 L9 L10 L11 L12 C3 A7 L62 L63 L64 against normal blind 10
extrude "Extrusion16" cut sketch "Skizze5" profile of L1 L2 L3 L4 L5 L6 L7 L8 L9 L10 L11 L12 C3 against normal blind 2.2
extrude "Extrusion17" new body sketch "Skizze5" profile of L1 L38 L39 L40 L41 L42 L43 L44 L45 L46 L47 L48 C2 A4 L59 L60 L65 L66 against normal blind 10
extrude "Extrusion18" cut sketch "Skizze5" profile of L1 L38 L39 L40 L41 L42 L43 L44 L45 L46 L47 L48 C2 against normal blind 2.2
combine "Kombinieren3"
extrude "Extrusion8" cut sketch "Skizze8" profile of L1 C1 against normal blind 107.88
extrude "Extrusion9" cut sketch "Skizze8" profile of L1 C2 C3 against normal blind 101.138
extrude "Extrusion10" add sketch "Skizze5" profile of C1 against normal blind 10
extrude "Extrusion19" cut sketch "Skizze5" profile of L1 C1 against normal blind 2.2
fillet "Abrundung2" radius 1
split "Teilen3" bodies "lid_W150xD95xH20 (2)"
remove_body "Körper entfernen1"
remove_body "Körper entfernen2"
fillet "Abrundung3" radius 1
offset_faces "Flächen versetzen3" distance 0.1
offset_faces "Flächen versetzen4" distance 0.1
offset_faces "Flächen versetzen5" distance -0.1
offset_faces "Flächen versetzen6" distance -0.1
extrude "Extrusion20" add of existing geometry blind 0.001
sketch "Skizze2" plane through (0, 0, 22) normal (0, 0, 1) x axis (-1, 0, 0)
  line L1 (75.7516, -3.8869) -> (74.202, -3.8821)
  line L2 (76.7489, -26.8162) -> (76.7485, -4.8869)
  line L3 (76.7497, -26.8162) -> (76.7489, -26.8162)
  line L4 (76.75, -45.3967) -> (76.7497, -26.8162)
  line L5 (76.7137, -45.8855) -> (76.75, -45.3967)
  line L6 (76.5868, -46.4537) -> (76.7137, -45.8855)
  line L7 (76.3699, -47.0013) -> (76.5868, -46.4537)
  line L8 (76.0702, -47.5081) -> (76.3699, -47.0013)
  line L9 (75.6956, -47.961) -> (76.0702, -47.5081)
  line L10 (75.2534, -48.351) -> (75.6956, -47.961)
  line L11 (74.7561, -48.6666) -> (75.2534, -48.351)
  line L12 (74.2155, -48.9006) -> (74.7561, -48.6666)
  line L13 (73.6446, -49.0471) -> (74.2155, -48.9006)
  line L14 (73.0981, -49.0987) -> (73.6446, -49.0471)
  line L15 (44.5718, -49.099) -> (73.0981, -49.0987)
  line L16 (44.5718, -49.0991) -> (44.5718, -49.099)
  line L17 (-56.0492, -49.0991) -> (44.5718, -49.0991)
  line L18 (-56.0492, -49.1001) -> (-56.0492, -49.0991)
  line L19 (-73.0463, -49.1003) -> (-56.0492, -49.1001)
  line L20 (-73.5352, -49.064) -> (-73.0463, -49.1003)
  line L21 (-74.1034, -48.937) -> (-73.5352, -49.064)
  line L22 (-74.6511, -48.7202) -> (-74.1034, -48.937)
  line L23 (-75.1581, -48.4203) -> (-74.6511, -48.7202)
  line L24 (-75.6123, -48.0443) -> (-75.1581, -48.4203)
  line L25 (-76.001, -47.6033) -> (-75.6123, -48.0443)
  line L26 (-76.3164, -47.1063) -> (-76.001, -47.6033)
  line L27 (-76.5503, -46.5658) -> (-76.3164, -47.1063)
  line L28 (-76.6968, -45.9949) -> (-76.5503, -46.5658)
  line L29 (-76.7485, -45.4483) -> (-76.6968, -45.9949)
  line L30 (-76.7487, -29.3162) -> (-76.7485, -45.4483)
  line L31 (-76.7495, -29.3162) -> (-76.7487, -29.3162)
  line L32 (-76.7499, -4.8661) -> (-76.7495, -29.3162)
  line L33 (-74.2621, -3.8625) -> (-75.7523, -3.8661)
  line L34 (-70.6287, 1.3933) -> (-70.6209, -0.1946)
  line L35 (-56.0492, 2.3984) -> (-69.6287, 2.3982)
  line L36 (-55.4492, 2.3984) -> (-56.0492, 2.3984)
  line L37 (-15.0491, 2.3988) -> (-55.4492, 2.3984)
  line L38 (-15.0491, 2.3984) -> (-15.0491, 2.3988)
  line L39 (-14.4491, 2.3984) -> (-15.0491, 2.3984)
  line L40 (-14.4491, 2.3988) -> (-14.4491, 2.3984)
  line L41 (-4.6759, 2.3989) -> (-14.4491, 2.3988)
  line L42 (-3.6759, 0.4365) -> (-3.6759, 1.3989)
  line L43 (3.6241, 1.399) -> (3.6241, 0.4365)
  line L44 (41.9495, 2.3994) -> (4.6241, 2.399)
  line L45 (41.9495, 2.3984) -> (41.9495, 2.3994)
  line L46 (42.5495, 2.3984) -> (41.9495, 2.3984)
  line L47 (42.5495, 2.3994) -> (42.5495, 2.3984)
  line L48 (69.4875, 2.3997) -> (42.5495, 2.3994)
  line L49 (70.4868, -0.1536) -> (70.4875, 1.3992)
  line L50 (77.0087, 2.7842) -> (77.6054, 2.1072)
  line L51 (76.3118, 3.361) -> (77.0087, 2.7842)
  line L52 (75.5337, 3.8212) -> (76.3118, 3.361)
  line L53 (74.6933, 4.154) -> (75.5337, 3.8212)
  line L54 (73.8289, 4.3472) -> (74.6933, 4.154)
  line L55 (73.1205, 4.3997) -> (73.8289, 4.3472)
  line L56 (-73.1923, 4.3982) -> (73.1205, 4.3997)
  line L57 (-73.9894, 4.3229) -> (-73.1923, 4.3982)
  line L58 (-74.8653, 4.0981) -> (-73.9894, 4.3229)
  line L59 (-75.6949, 3.7391) -> (-74.8653, 4.0981)
  line L60 (-76.4582, 3.2546) -> (-75.6949, 3.7391)
  line L61 (-77.1366, 2.6563) -> (-76.4582, 3.2546)
  line L62 (-77.7116, 1.961) -> (-77.1366, 2.6563)
  line L63 (-78.1715, 1.1835) -> (-77.7116, 1.961)
  line L64 (-78.5043, 0.343) -> (-78.1715, 1.1835)
  line L65 (-78.6974, -0.5214) -> (-78.5043, 0.343)
  line L66 (-78.75, -1.2298) -> (-78.6974, -0.5214)
  line L67 (-78.7498, -10.7646) -> (-78.75, -1.2298)
  line L68 (-78.7587, -10.8019) -> (-78.7498, -10.7646)
  line L69 (-78.7498, -11.3207) -> (-78.7587, -10.8019)
  line L70 (-78.7496, -22.2851) -> (-78.7498, -11.3207)
  line L71 (-78.7572, -22.3136) -> (-78.7496, -22.2851)
  line L72 (-78.757, -23.5927) -> (-78.7572, -22.3136)
  line L73 (-78.7496, -23.6181) -> (-78.757, -23.5927)
  line L74 (-78.7495, -28.0662) -> (-78.7496, -23.6181)
  line L75 (-78.7488, -28.0662) -> (-78.7495, -28.0662)
  line L76 (-78.7487, -34.1454) -> (-78.7488, -28.0662)
  line L77 (-78.7493, -34.1513) -> (-78.7487, -34.1454)
  line L78 (-78.7487, -34.1551) -> (-78.7493, -34.1513)
  line L79 (-78.7485, -45.5426) -> (-78.7487, -34.1551)
  line L80 (-78.744, -45.5898) -> (-78.7485, -45.5426)
  line L81 (-78.7497, -45.6324) -> (-78.744, -45.5898)
  line L82 (-78.7358, -45.6765) -> (-78.7497, -45.6324)
  line L83 (-78.6732, -46.3397) -> (-78.7358, -45.6765)
  line L84 (-78.4484, -47.2156) -> (-78.6732, -46.3397)
  line L85 (-78.0894, -48.0451) -> (-78.4484, -47.2156)
  line L86 (-77.6054, -48.8077) -> (-78.0894, -48.0451)
  line L87 (-77.0087, -49.4847) -> (-77.6054, -48.8077)
  line L88 (-76.3119, -50.0615) -> (-77.0087, -49.4847)
  line L89 (-75.5337, -50.5217) -> (-76.3119, -50.0615)
  line L90 (-74.6932, -50.8545) -> (-75.5337, -50.5217)
  line L91 (-73.8289, -51.0477) -> (-74.6932, -50.8545)
  line L92 (-73.1205, -51.1003) -> (-73.8289, -51.0477)
  line L93 (-70.6456, -51.1002) -> (-73.1205, -51.1003)
  line L94 (-70.5833, -51.1101) -> (-70.6456, -51.1002)
  line L95 (-70.4873, -51.1002) -> (-70.5833, -51.1101)
  line L96 (-64.3433, -51.1002) -> (-70.4873, -51.1002)
  line L97 (-64.3433, -51.8441) -> (-64.3433, -51.1002)
  line L98 (-58.3433, -51.8441) -> (-64.3433, -51.8441)
  line L99 (-58.3433, -51.1001) -> (-58.3433, -51.8441)
  line L100 (-47.5994, -51.1) -> (-58.3433, -51.1001)
  line L101 (-47.561, -51.1081) -> (-47.5994, -51.1)
  line L102 (-47.3834, -51.1) -> (-47.561, -51.1081)
  line L103 (-41.3433, -51.0999) -> (-47.3834, -51.1)
  line L104 (-41.3433, -51.8441) -> (-41.3433, -51.0999)
  line L105 (-35.3433, -51.8441) -> (-41.3433, -51.8441)
  line L106 (-35.3433, -51.0999) -> (-35.3433, -51.8441)
  line L107 (-24.5609, -51.0998) -> (-35.3433, -51.0999)
  line L108 (-24.5366, -51.1062) -> (-24.5609, -51.0998)
  line L109 (-23.2573, -51.1061) -> (-24.5366, -51.1062)
  line L110 (-23.2355, -51.0997) -> (-23.2573, -51.1061)
  line L111 (-13.0448, -51.0996) -> (-23.2355, -51.0997)
  line L112 (-13.0255, -51.1052) -> (-13.0448, -51.0996)
  line L113 (-11.7462, -51.1051) -> (-13.0255, -51.1052)
  line L114 (-11.7254, -51.0996) -> (-11.7462, -51.1051)
  line L115 (-0.5072, -51.0995) -> (-11.7254, -51.0996)
  line L116 (-0.2329, -51.1041) -> (-0.5072, -51.0995)
  line L117 (-0.2134, -51.0995) -> (-0.2329, -51.1041)
  line L118 (11.1949, -51.0994) -> (-0.2134, -51.0995)
  line L119 (11.2782, -51.1032) -> (11.1949, -51.0994)
  line L120 (11.2962, -51.0994) -> (11.2782, -51.1032)
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  point P36 (-76.7499, -4.8661)
  point P188 (-76.7499, -4.8661)
  point P189 (-78.7499, -4.8661)
  point P43 (-69.6287, 2.3982)
  point P190 (-69.6287, 2.3982)
  point P191 (-69.6287, 4.3982)
  point P58 (4.6241, 2.399)
  point P192 (4.6241, 2.399)
  point P193 (4.6241, 4.399)
  point P51 (-4.6759, 2.3989)
  point P194 (-4.6759, 2.3989)
  point P195 (-4.6759, 4.3989)
  point P4 (76.7485, -4.8869)
  point P196 (76.7485, -4.8869)
  point P64 (69.4875, 2.3997)
  point P198 (69.4875, 2.3997)
  point P199 (69.4875, 4.3997)
  point P183 (78.7485, -1.1579)
  point P214 (78.7485, -1.1579)
  point P184 (78.7358, -1.024)
  point P215 (78.7358, -1.024)
  coincident P36 P188
  coincident L67 P189
  coincident P43 P190
  coincident L56 P191
  coincident P58 P192
  coincident L56 P193
  coincident P51 P194
  coincident L56 P195
  coincident P4 P196
  coincident P64 P198
  coincident L56 P199
  coincident P183 P214
  coincident P184 P215
  dimension "d94" = -0.9
  dimension "d95" = -0.9
  dimension "d96" = -0.9
extrude "Extrusion2" new body sketch "Skizze2" along normal blind 3.978
sketch "Skizze3" plane through (0, 0, 22) normal (0, 0, -1) x axis (1, 0, 0)
  line L1 (-74.6486, 4.3998) -> (74.6267, 4.3982)
  line L2 (-75.4335, 4.1218) -> (-74.6486, 4.3998)
  line L3 (-76.2604, 3.6728) -> (-75.4335, 4.1218)
  line L4 (-77.0079, 3.099) -> (-76.2604, 3.6728)
  line L5 (-77.6547, 2.4173) -> (-77.0079, 3.099)
  line L6 (-78.1871, 1.6426) -> (-77.6547, 2.4173)
  line L7 (-78.5922, 0.7932) -> (-78.1871, 1.6426)
  line L8 (-78.8596, -0.1097) -> (-78.5922, 0.7932)
  line L9 (-78.9823, -1.0422) -> (-78.8596, -0.1097)
  line L10 (-78.986, -28.0662) -> (-78.9823, -1.0422)
  line L11 (-78.9923, -28.0662) -> (-78.986, -28.0662)
  line L12 (-78.9946, -45.3556) -> (-78.9923, -28.0662)
  line L13 (-78.9578, -45.9816) -> (-78.9946, -45.3556)
  line L14 (-78.7863, -46.9071) -> (-78.9578, -45.9816)
  line L15 (-78.4721, -47.7945) -> (-78.7863, -46.9071)
  line L16 (-78.0231, -48.6214) -> (-78.4721, -47.7945)
  line L17 (-77.4515, -49.3665) -> (-78.0231, -48.6214)
  line L18 (-76.7688, -50.0146) -> (-77.4515, -49.3665)
  line L19 (-75.9928, -50.5481) -> (-76.7688, -50.0146)
  line L20 (-75.1435, -50.9532) -> (-75.9928, -50.5481)
  line L21 (-74.2406, -51.2206) -> (-75.1435, -50.9532)
  line L22 (-73.3081, -51.3433) -> (-74.2406, -51.2206)
  line L23 (73.0054, -51.3556) -> (-73.3081, -51.3433)
  line L24 (73.6314, -51.3188) -> (73.0054, -51.3556)
  line L25 (74.5569, -51.1473) -> (73.6314, -51.3188)
  line L26 (75.4442, -50.8331) -> (74.5569, -51.1473)
  line L27 (76.2712, -50.3841) -> (75.4442, -50.8331)
  line L28 (77.0186, -49.8103) -> (76.2712, -50.3841)
  line L29 (77.6654, -49.1285) -> (77.0186, -49.8103)
  line L30 (78.1978, -48.3538) -> (77.6654, -49.1285)
  line L31 (78.603, -47.5045) -> (78.1978, -48.3538)
  line L32 (78.8704, -46.6016) -> (78.603, -47.5045)
  line L33 (78.9931, -45.6691) -> (78.8704, -46.6016)
  line L34 (78.9954, -28.0662) -> (78.9931, -45.6691)
  line L35 (79.0018, -28.0662) -> (78.9954, -28.0662)
  line L36 (79.0054, -1.3556) -> (79.0018, -28.0662)
  line L37 (78.9685, -0.7297) -> (79.0054, -1.3556)
  line L38 (78.797, 0.1959) -> (78.9685, -0.7297)
  line L39 (78.4828, 1.0832) -> (78.797, 0.1959)
  line L40 (78.0338, 1.9102) -> (78.4828, 1.0832)
  line L41 (77.4622, 2.6553) -> (78.0338, 1.9102)
  line L42 (76.7795, 3.3034) -> (77.4622, 2.6553)
  line L43 (76.0036, 3.8368) -> (76.7795, 3.3034)
  line L44 (75.1543, 4.242) -> (76.0036, 3.8368)
  line L45 (74.6267, 4.3982) -> (75.1543, 4.242)
  line L46 (75.4954, -28.0662) -> (75.5018, -28.0662)
  line L47 (75.4931, -45.5565) -> (75.4954, -28.0662)
  line L48 (-73.1956, -47.8433) -> (73.0033, -47.8556)
  line L49 (-75.4923, -28.0662) -> (-75.4946, -45.3537)
  line L50 (-75.486, -28.0662) -> (-75.4923, -28.0662)
  line L51 (-75.4823, -1.1548) -> (-75.486, -28.0662)
  line L52 (73.2063, 1.1321) -> (-72.9926, 1.1444)
  line L53 (75.5018, -28.0662) -> (75.5054, -1.3576)
  line L54 (3.6759, 1.3989) -> (3.6759, 0.4365)
  line L55 (4.6759, 3.4989) -> (4.6759, 2.3989)
  line L56 (-4.6241, 3.499) -> (4.6759, 3.4989)
  line L57 (-4.6241, 2.399) -> (-4.6241, 3.499)
  line L58 (-3.6241, 0.4365) -> (-3.6241, 1.399)
  line L59 (-76.111, 2.359) -> (-75.7926, 2.6225)
  line L60 (-76.8834, 1.5652) -> (-76.7298, 1.7396)
  line L61 (-77.2915, 0.9221) -> (-76.8834, 1.5652)
  line L62 (-77.5943, 0.2226) -> (-77.2915, 0.9221)
  line L63 (-77.7838, -0.516) -> (-77.5943, 0.2226)
  line L64 (-77.8485, -1.2003) -> (-77.7838, -0.516)
  line L65 (-77.8485, -4.8869) -> (-77.8485, -1.2003)
  line L66 (-76.7485, -4.8869) -> (-77.8485, -4.8869)
  line L67 (-74.202, -3.8821) -> (-75.7516, -3.8869)
  line L68 (-70.4875, 1.3992) -> (-70.4868, -0.1536)
  line L69 (-69.4875, 3.4997) -> (-69.4875, 2.3997)
  line L70 (-73.0871, 3.4997) -> (-69.4875, 3.4997)
  line L71 (-73.6968, 3.4545) -> (-73.0871, 3.4997)
  line L72 (-74.4278, 3.2911) -> (-73.6968, 3.4545)
  line L73 (-75.1365, 3.0105) -> (-74.4278, 3.2911)
  line L74 (-75.7926, 2.6225) -> (-75.1365, 3.0105)
  line L75 (75.7523, -3.8661) -> (74.2621, -3.8625)
  line L76 (77.8499, -4.8661) -> (76.7499, -4.8661)
  line L77 (77.85, -1.2631) -> (77.8499, -4.8661)
  line L78 (77.8047, -0.6535) -> (77.85, -1.2631)
  line L79 (77.6414, 0.0776) -> (77.8047, -0.6535)
  line L80 (77.3608, 0.7863) -> (77.6414, 0.0776)
  line L81 (76.9729, 1.442) -> (77.3608, 0.7863)
  line L82 (76.8724, 1.5635) -> (76.9729, 1.442)
  line L83 (75.9161, 2.5327) -> (76.2518, 2.2367)
  line L84 (75.2724, 2.9413) -> (75.9161, 2.5327)
  line L85 (74.5729, 3.244) -> (75.2724, 2.9413)
  line L86 (73.8343, 3.4336) -> (74.5729, 3.244)
  line L87 (73.1499, 3.4982) -> (73.8343, 3.4336)
  line L88 (69.6287, 3.4982) -> (73.1499, 3.4982)
  line L89 (69.6287, 2.3982) -> (69.6287, 3.4982)
  line L90 (70.6209, -0.1946) -> (70.6287, 1.3933)
  curve K1 (73.1222, -0.8742) -> (73.2063, 1.1321)
  line L91 (-72.9926, 1.1444) -> (73.2063, 1.1321)
  curve K2 (-72.9904, -0.8556) -> (-72.9926, 1.1444)
  line L92 (73.1246, -0.8679) -> (-72.9904, -0.8556)
  line L93 (73.5018, -28.0662) -> (73.4954, -28.0662)
  line L94 (73.5054, -1.3597) -> (73.5018, -28.0662)
  line L95 (-72.9904, -0.8556) -> (73.1246, -0.8679)
  line L96 (-73.486, -28.0662) -> (-73.4824, -1.268)
  line L97 (-73.4923, -28.0662) -> (-73.486, -28.0662)
  line L98 (-73.4946, -45.3516) -> (-73.4923, -28.0662)
  line L99 (73.0012, -45.8556) -> (-73.1138, -45.8434)
  line L100 (73.4954, -28.0662) -> (73.4931, -45.4723)
  arc A1 centre (72.9978, -45.352) radius 2.5037 clockwise from (75.4931, -45.5565) to (73.0033, -47.8556)
  arc A2 centre (-72.9911, -45.3482) radius 2.5036 clockwise from (-73.1956, -47.8433) to (-75.4946, -45.3537)
  arc A3 centre (-72.987, -1.3593) radius 2.5037 clockwise from (-75.4823, -1.1548) to (-72.9926, 1.1444)
  arc A4 centre (73.0018, -1.3631) radius 2.5036 clockwise from (73.2063, 1.1321) to (75.5054, -1.3576)
  circle C1 centre (0.0259, 0.4365) radius 3.05
  arc A5 centre (4.6759, 1.3989) radius 1 clockwise from (3.6759, 1.3989) to (4.6759, 2.3989)
  arc A6 centre (-4.6241, 1.399) radius 1 clockwise from (-4.6241, 2.399) to (-3.6241, 1.399)
  arc A7 centre (0.0259, 0.4365) radius 3.65 clockwise from (3.6759, 0.4365) to (-3.6241, 0.4365)
  arc A8 centre (-74.2135, -0.1554) radius 3.15 clockwise from (-76.111, 2.359) to (-76.7298, 1.7396)
  arc A9 centre (-75.7485, -4.8869) radius 1 clockwise from (-76.7485, -4.8869) to (-75.7516, -3.8869)
  arc A10 centre (-74.2135, -0.1554) radius 3.7267 clockwise from (-70.4868, -0.1536) to (-74.202, -3.8821)
  arc A11 centre (-69.4875, 1.3997) radius 1 clockwise from (-70.4875, 1.3992) to (-69.4875, 2.3997)
  arc A12 centre (75.7499, -4.8661) radius 1 clockwise from (75.7523, -3.8661) to (76.7499, -4.8661)
  arc A13 centre (74.2708, -0.2125) radius 3.15 clockwise from (76.8724, 1.5635) to (76.2518, 2.2367)
  arc A14 centre (69.6287, 1.3982) radius 1 clockwise from (69.6287, 2.3982) to (70.6287, 1.3933)
  arc A15 centre (74.2708, -0.2125) radius 3.65 clockwise from (74.2621, -3.8625) to (70.6209, -0.1946)
  arc A16 centre (73.0018, -1.3631) radius 0.5036 clockwise from (73.1222, -0.8742) to (73.5054, -1.3597)
  arc A17 centre (-72.987, -1.3593) radius 0.5037 clockwise from (-73.4824, -1.268) to (-72.9904, -0.8556)
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extrude "Extrusion3" new body sketch "Skizze3" profile of C1 L92 L95 against normal blind 0.06
extrude "Extrusion4" new body of existing geometry blind -3.5
extrude "Extrusion5" new body of existing geometry blind 2
extrude "Extrusion6" new body of existing geometry blind 0.519
extrude "Extrusion7" new body of existing geometry blind 0.623
extrude "Extrusion8" cut of existing geometry blind -3.5
extrude "Extrusion9" new body of existing geometry blind 3.5
combine "Kombinieren1"
offset_faces "Flächen versetzen1" distance -1.25
extrude "Extrusion10" cut of existing geometry blind -3.5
